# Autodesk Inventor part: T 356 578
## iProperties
Company: Mayer & Müller AG Schaltgeräte
Created: 2006-01
Part Number: T 356 578
Material: 2.0402.26
Document SubType Name: Modeling
Designer: I.Baliuc
Manufacturer: Standard
Standards Organization: Custom
Description: Bolzen
Density: 8.2 g/cm^3
HalbzeugNorm: DIN 1756
Zweck: für Kontaktträger (Strombahn)
Abmessung: Rd 10 - 25
Author: T.Messerschmitt
Keywords: 267031
Revision Number: 356578
Comments: die Senkung geändert von 0,5 auf 1 mm
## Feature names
1. Drehung1 [Revolution]
